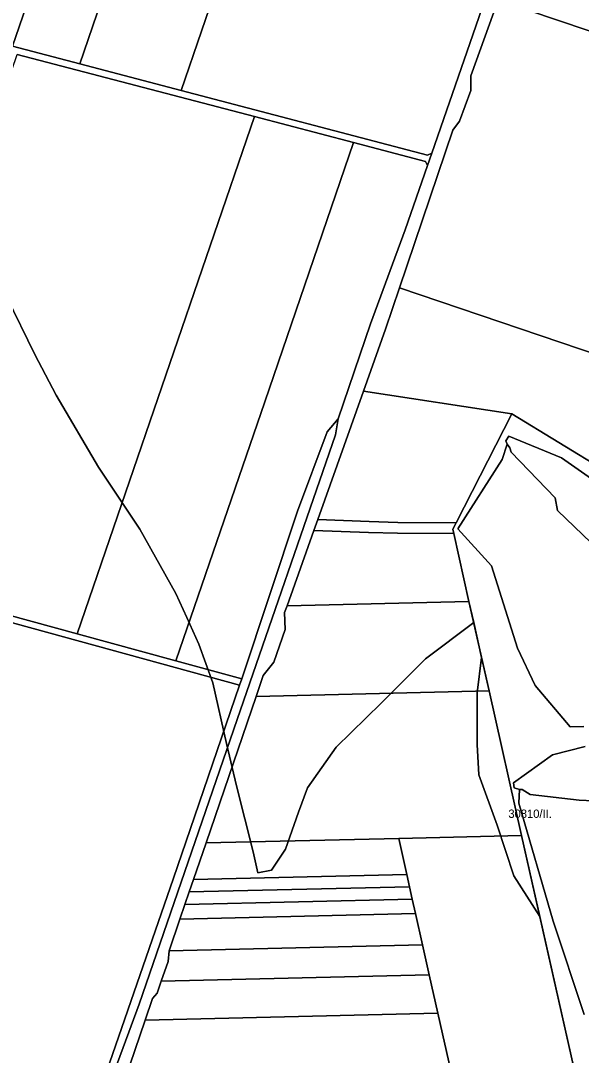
# Model space of a CAD drawing. Extents: x -545779 to -541342, y -1153413 to -1149956.
# Drawn here: x -544701 to -544366, y -1152262 to -1151643 of the extents above; entities that cross this region are included whole.
import ezdxf

# ---------------------------------------------------------------- set-up
doc = ezdxf.new("R2010")
doc.units = 0
for name, color, linetype in [('95560013', 7, 'Continuous'), ('95630013', 7, 'Continuous'), ('95640013', 7, 'Continuous'), ('95660013', 7, 'Continuous')]:
    doc.layers.add(name, color=color, linetype=linetype)

msp = doc.modelspace()

# ---------------------------------------------------------------- linework, layer by layer
at = {"layer": '95560013'}
for points in [[(-544665.98, -1151668.72), (-544629.97, -1151563.59), (-544593.95, -1151458.46), (-544540.71, -1151449.17), (-544572.23, -1151542.64), (-544556.71, -1151542.54), (-544605.38, -1151684.64)], [(-544665.98, -1151668.72), (-544706.17, -1151658.17), (-544673.36, -1151562.38), (-544640.54, -1151466.58), (-544593.95, -1151458.46), (-544629.97, -1151563.59)], [(-544646.97, -1151467.7), (-544640.54, -1151466.58), (-544673.36, -1151562.38), (-544706.17, -1151658.17), (-544726.4, -1151652.86), (-544663.43, -1151469.03)], [(-544411.63, -1151619.63), (-544385.88, -1151566.12), (-544374.27, -1151550.18), (-544348.98, -1151514.49), (-544275.88, -1151539.22), (-544308.61, -1151666.67), (-544415.57, -1151630.49)], [(-544455.29, -1151722.05), (-544457.82, -1151723.4), (-544605.38, -1151684.64), (-544556.71, -1151542.54), (-544482.08, -1151542.04), (-544385.47, -1151546.37), (-544402.51, -1151579.84), (-544425.47, -1151635.75)], [(-544319.09, -1151706.41), (-544325.87, -1151749.51), (-544330.86, -1151782.36), (-544337.64, -1151820.46), (-544340.91, -1151841.16), (-544342.22, -1151847.52), (-544474.71, -1151802.71), (-544442.81, -1151708.38), (-544438.68, -1151702.96), (-544432.02, -1151684.69), (-544431.97, -1151675.83), (-544415.57, -1151630.49), (-544308.61, -1151666.67), (-544309.29, -1151669.8)], [(-544561.49, -1151700.3), (-544614.46, -1151854.98), (-544667.45, -1152009.7), (-544808.85, -1151971.06), (-544756.1, -1151817.04), (-544703.36, -1151663.03)], [(-544667.45, -1152009.7), (-544614.46, -1151854.98), (-544561.49, -1151700.3), (-544502.24, -1151715.86), (-544555.32, -1151870.84), (-544608.4, -1152025.83)], [(-544555.32, -1151870.84), (-544502.24, -1151715.86), (-544459.14, -1151727.18), (-544457.88, -1151729.54), (-544471.2, -1151768.07), (-544492.05, -1151824.34), (-544511.33, -1151881.16), (-544517.9, -1151888.93), (-544535.68, -1151936.25), (-544569.04, -1152036.59), (-544608.4, -1152025.83)], [(-544346.23, -1151866.95), (-544340.28, -1151867.89), (-544347.9, -1151903.54), (-544351.13, -1151912.42), (-544407.5, -1151878.02), (-544496.26, -1151864.52), (-544483.08, -1151827.46), (-544474.71, -1151802.71), (-544342.22, -1151847.52)], [(-544475.66, -1151943.05), (-544492.9, -1151942.53), (-544523.61, -1151941.41), (-544496.26, -1151864.52), (-544407.5, -1151878.02), (-544440.77, -1151943.22)], [(-544541.95, -1151992.96), (-544525.9, -1151947.83), (-544493.12, -1151949.03), (-544475.78, -1151949.55), (-544442.21, -1151949.72), (-544433.09, -1151990.35)], [(-544421.06, -1152043.91), (-544560.42, -1152047.27), (-544556.17, -1152034.56), (-544549.76, -1152026.71), (-544543.02, -1152007.12), (-544543.4, -1151997.05), (-544541.95, -1151992.96), (-544433.09, -1151990.35)], [(-544829.11, -1152336.09), (-544771.74, -1152168.57), (-544714.36, -1152001.03), (-544570.31, -1152040.39), (-544599.8, -1152126.71), (-544609.92, -1152155.93), (-544651.83, -1152276.93), (-544699.22, -1152404.28), (-544701.77, -1152403.03), (-544759.32, -1152374.84), (-544795.95, -1152353.72), (-544802.85, -1152349.74)], [(-544475.15, -1152132.07), (-544590.33, -1152134.84), (-544560.42, -1152047.27), (-544421.06, -1152043.91), (-544401.66, -1152130.3)], [(-544597.88, -1152156.75), (-544590.33, -1152134.84), (-544475.15, -1152132.07), (-544470.29, -1152153.68)], [(-544475.15, -1152132.07), (-544401.66, -1152130.3), (-544370.25, -1152270.16), (-544443.74, -1152271.92), (-544451.66, -1152236.63), (-544456.82, -1152213.7), (-544460.85, -1152195.73), (-544465.07, -1152176.96), (-544466.98, -1152168.45), (-544468.65, -1152160.98), (-544470.29, -1152153.68)], [(-544470.29, -1152153.68), (-544468.65, -1152160.98), (-544600.43, -1152164.15), (-544597.88, -1152156.75)], [(-544600.43, -1152164.15), (-544468.65, -1152160.98), (-544466.98, -1152168.45), (-544603.03, -1152171.72)], [(-544465.07, -1152176.96), (-544606, -1152180.35), (-544603.03, -1152171.72), (-544466.98, -1152168.45)], [(-544460.85, -1152195.73), (-544612.56, -1152199.38), (-544606, -1152180.35), (-544465.07, -1152176.96)], [(-544617.23, -1152217.55), (-544613.15, -1152205.7), (-544612.56, -1152199.38), (-544460.85, -1152195.73), (-544456.82, -1152213.7)], [(-544622.37, -1152227.91), (-544619.66, -1152224.61), (-544617.23, -1152217.55), (-544456.82, -1152213.7), (-544451.66, -1152236.63), (-544626.78, -1152240.84)], [(-544451.66, -1152236.63), (-544443.74, -1152271.92), (-544638.99, -1152276.62), (-544626.78, -1152240.84)]]:
    msp.add_lwpolyline(points, close=True, dxfattribs=at)
at = {"layer": '95630013'}
for points in [[(-544364.32, -1152065.07), (-544372.46, -1152065.31), (-544393.46, -1152040.56), (-544404.14, -1152018.33), (-544419.66, -1151969.02), (-544439.77, -1151946.87), (-544413.3, -1151905.39), (-544410.34, -1151896.31), (-544408.56, -1151898.41), (-544407.88, -1151901.07), (-544381.57, -1151928.44), (-544380.21, -1151935.96), (-544359.92, -1151955.29)], [(-544364.14, -1152237.5), (-544382.81, -1152181.59), (-544403.24, -1152110.93), (-544402.96, -1152102.78), (-544401.17, -1152102.77), (-544396.39, -1152105.83), (-544367.17, -1152109.21), (-544358.62, -1152109.71)]]:
    msp.add_lwpolyline(points, dxfattribs=at)
at = {"layer": '95640013'}
for points in [[(-544415.57, -1151630.49), (-544431.97, -1151675.83), (-544432.02, -1151684.69), (-544438.68, -1151702.96), (-544442.81, -1151708.38), (-544474.71, -1151802.71), (-544483.08, -1151827.46), (-544496.26, -1151864.52), (-544523.61, -1151941.41), (-544525.9, -1151947.83), (-544541.95, -1151992.96), (-544543.4, -1151997.05), (-544543.02, -1152007.12), (-544549.76, -1152026.71), (-544556.17, -1152034.56), (-544560.42, -1152047.27), (-544590.33, -1152134.84), (-544597.88, -1152156.75), (-544600.43, -1152164.15), (-544603.03, -1152171.72), (-544606, -1152180.35), (-544612.56, -1152199.38), (-544613.15, -1152205.7), (-544617.23, -1152217.55), (-544619.66, -1152224.61), (-544622.37, -1152227.91), (-544626.78, -1152240.84), (-544638.99, -1152276.62)], [(-544696.71, -1152410.52), (-544630.44, -1152231.35), (-544571.74, -1152060.98), (-544513.04, -1151890.62), (-544511.33, -1151881.16), (-544492.05, -1151824.34), (-544471.2, -1151768.07), (-544457.88, -1151729.54), (-544455.29, -1151722.05), (-544425.47, -1151635.75)], [(-544706.17, -1151658.17), (-544665.98, -1151668.72), (-544605.38, -1151684.64), (-544457.82, -1151723.4), (-544455.29, -1151722.05), (-544457.88, -1151729.54), (-544459.14, -1151727.18), (-544502.24, -1151715.86), (-544561.49, -1151700.3), (-544703.36, -1151663.03)], [(-544370.25, -1152270.16), (-544401.66, -1152130.3), (-544421.06, -1152043.91), (-544433.09, -1151990.35), (-544442.21, -1151949.72), (-544442.79, -1151947.17), (-544440.77, -1151943.22), (-544407.5, -1151878.02), (-544351.13, -1151912.42)], [(-544343.86, -1151928.06), (-544377.68, -1151904.35), (-544409.31, -1151891.54), (-544411.13, -1151894.33), (-544410.34, -1151896.31), (-544413.3, -1151905.39), (-544439.77, -1151946.87), (-544419.66, -1151969.02), (-544404.14, -1152018.33), (-544393.46, -1152040.56), (-544372.46, -1152065.31), (-544364.32, -1152065.07)], [(-544358.62, -1152109.71), (-544367.17, -1152109.21), (-544396.39, -1152105.83), (-544401.17, -1152102.77), (-544402.96, -1152102.78), (-544406.05, -1152101.88), (-544406.48, -1152098.77), (-544383.11, -1152082.09), (-544363.49, -1152077.04)], [(-544363.49, -1152077.04), (-544383.11, -1152082.09), (-544406.48, -1152098.77), (-544406.05, -1152101.88), (-544402.96, -1152102.78), (-544403.24, -1152110.93), (-544382.81, -1152181.59), (-544364.14, -1152237.5)]]:
    msp.add_lwpolyline(points, dxfattribs=at)
for points in [[(-545010.11, -1151920.23), (-545033.07, -1151913.96), (-545076.62, -1151902.06), (-545104.56, -1151894.42), (-545167.86, -1151877.12), (-545172.83, -1151879.3), (-545168.93, -1151867.91), (-545166.57, -1151873.32), (-545136.13, -1151881.64), (-545080.6, -1151896.81), (-544954.48, -1151931.27), (-544862.19, -1151956.49), (-544808.85, -1151971.06), (-544667.45, -1152009.7), (-544608.4, -1152025.83), (-544569.04, -1152036.59), (-544570.31, -1152040.39), (-544714.36, -1152001.03), (-544842.54, -1151966.01), (-544992.14, -1151925.13)], [(-544570.31, -1152040.39), (-544569.04, -1152036.59), (-544535.68, -1151936.25), (-544517.9, -1151888.93), (-544511.33, -1151881.16), (-544513.04, -1151890.62), (-544571.74, -1152060.98), (-544630.44, -1152231.35), (-544696.71, -1152410.52), (-544699.22, -1152404.28), (-544651.83, -1152276.93), (-544609.92, -1152155.93), (-544599.8, -1152126.71)], [(-544377.68, -1151904.35), (-544343.86, -1151928.06), (-544345.71, -1151931.05), (-544358.52, -1151948.28), (-544359.92, -1151955.29), (-544380.21, -1151935.96), (-544381.57, -1151928.44), (-544407.88, -1151901.07), (-544408.56, -1151898.41), (-544410.34, -1151896.31), (-544411.13, -1151894.33), (-544409.31, -1151891.54)], [(-544475.78, -1151949.55), (-544493.12, -1151949.03), (-544525.9, -1151947.83), (-544523.61, -1151941.41), (-544492.9, -1151942.53), (-544475.66, -1151943.05), (-544440.77, -1151943.22), (-544442.79, -1151947.17), (-544442.21, -1151949.72)]]:
    msp.add_lwpolyline(points, close=True, dxfattribs=at)
at = {"layer": '95660013'}
for points in [[(-544709.833, -1151807.884), (-544692.752, -1151842.596), (-544680.079, -1151866.839), (-544654.735, -1151910.091), (-544629.941, -1151947.007), (-544608.452, -1151985.576), (-544601.895, -1152000), (-544594.678, -1152015.881), (-544586.412, -1152039.022), (-544578.147, -1152075.387), (-544572.085, -1152100.732), (-544562.169, -1152140.128), (-544559.414, -1152152.8), (-544551.149, -1152151.148), (-544542.884, -1152138.475), (-544535.171, -1152116.435), (-544529.66, -1152101.834), (-544512.581, -1152077.591), (-544485.581, -1152051.144), (-544459.134, -1152024.696), (-544430.265, -1152002.927), (-544425.541, -1152023.959), (-544428.278, -1152045.083), (-544428.278, -1152075.938), (-544427.178, -1152094.121), (-544416.158, -1152124.149), (-544406.241, -1152154.453), (-544390.78, -1152178.746), (-544390.78, -1152178.746), (-544370.25, -1152270.16)], [(-544351.13, -1151912.42), (-544407.5, -1151878.02), (-544440.77, -1151943.22), (-544442.79, -1151947.17), (-544442.21, -1151949.72), (-544433.09, -1151990.35), (-544430.265, -1152002.927), (-544459.134, -1152024.696), (-544485.581, -1152051.144), (-544512.581, -1152077.591), (-544529.66, -1152101.834), (-544535.171, -1152116.435), (-544542.884, -1152138.475), (-544551.149, -1152151.148), (-544559.414, -1152152.8), (-544562.169, -1152140.128), (-544572.085, -1152100.732), (-544578.147, -1152075.387), (-544586.412, -1152039.022), (-544594.678, -1152015.881), (-544601.895, -1152000), (-544608.452, -1151985.576), (-544629.941, -1151947.007), (-544654.735, -1151910.091), (-544680.079, -1151866.839), (-544692.752, -1151842.596), (-544709.833, -1151807.884)], [(-544370.25, -1152270.16), (-544390.78, -1152178.746), (-544401.66, -1152130.3), (-544421.06, -1152043.91), (-544425.541, -1152023.959), (-544430.265, -1152002.927), (-544433.09, -1151990.35), (-544442.21, -1151949.72), (-544442.79, -1151947.17), (-544440.77, -1151943.22), (-544407.5, -1151878.02), (-544351.13, -1151912.42)]]:
    msp.add_lwpolyline(points, dxfattribs=at)
msp.add_lwpolyline([(-544428.278, -1152045.083), (-544425.541, -1152023.959), (-544421.06, -1152043.91), (-544401.66, -1152130.3), (-544390.78, -1152178.746), (-544406.241, -1152154.453), (-544416.158, -1152124.149), (-544427.178, -1152094.121), (-544428.278, -1152075.938)], close=True, dxfattribs=at)

# ---------------------------------------------------------------- texts
msp.add_text('30810/II.', height=5, rotation=0, dxfattribs=at).set_placement((-544409.529, -1152119.832))

doc.saveas('drawing.dxf')
